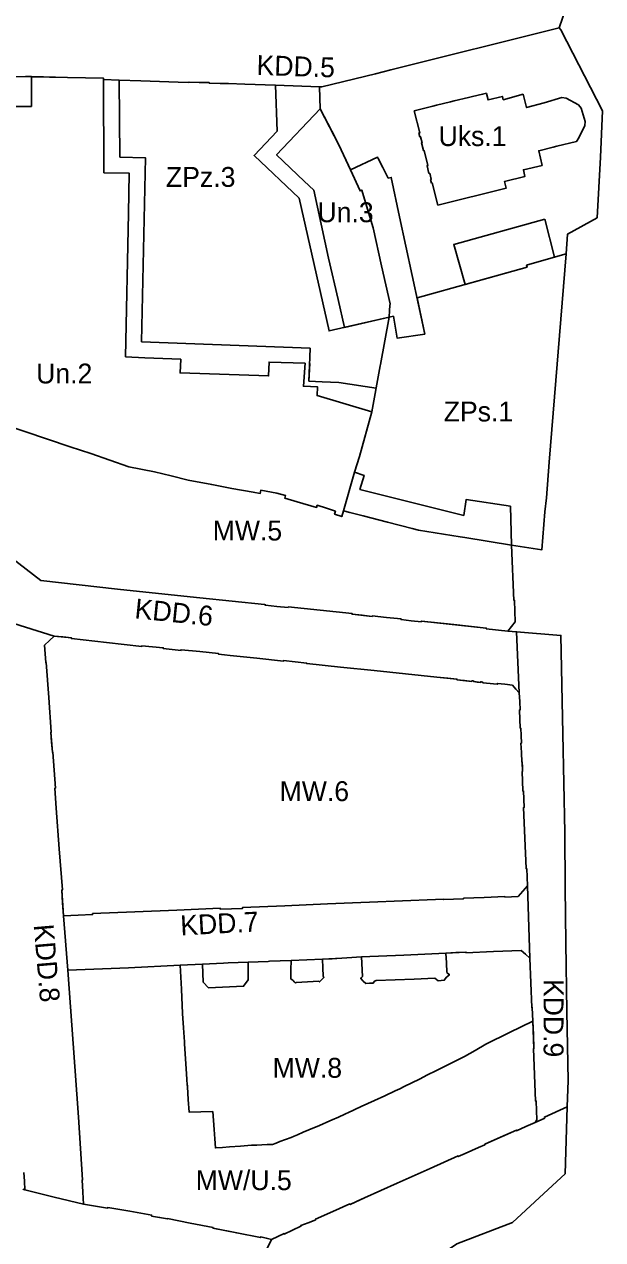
# Model space of a CAD drawing. Extents: x 7423893 to 7425332, y 5547241 to 5548246.
# Drawn here: x 7424503.9 to 7424649.3, y 5547447.3 to 5547753.2 of the extents above; entities that cross this region are included whole.
import ezdxf

# ---------------------------------------------------------------- set-up
doc = ezdxf.new("R2010")
doc.units = 0
for name, color, linetype in [('linie rozgraniczające', 7, 'Continuous'), ('nieprzekraczalne linie zabudowy', 7, 'Continuous'), ('obowiazujace linie zabudowy', 7, 'Continuous'), ('przeznaczenia terenów', 7, 'Continuous')]:
    doc.layers.add(name, color=color, linetype=linetype)

msp = doc.modelspace()

# ---------------------------------------------------------------- linework, layer by layer
at = {"layer": 'linie rozgraniczające'}
for p, q in [((7424638.32, 5547752.33), (7424647.15, 5547777.97)), ((7424527.77, 5547739.17), (7424527.86, 5547719.76)), ((7424602.61, 5547684.33), (7424604.56, 5547675.26)), ((7424575.62, 5547667.85), (7424575.42, 5547663.41)), ((7424493.58, 5547604.76), (7424511.39, 5547599.26)), ((7424612.65, 5547588.41), (7424607.57, 5547588.92)), ((7424630.36, 5547536.41), (7424630.95, 5547518.2)), ((7424514.83, 5547515.21), (7424513.72, 5547528.84)), ((7424516.17, 5547496.69), (7424514.83, 5547515.21)), ((7424566.05, 5547447.44), (7424558.82, 5547432.87))]:
    msp.add_line(p, q, dxfattribs=at)
for points in [[(7424578.1, 5547737.49), (7424578.64, 5547737.47), (7424592.15, 5547740.77), (7424596.05, 5547741.7), (7424638.32, 5547752.33)], [(7424638.32, 5547752.33), (7424638.76, 5547751.78), (7424649.27, 5547731.38), (7424648.72, 5547719.8), (7424647.91, 5547704.52), (7424640.47, 5547700.4), (7424640.07, 5547695.44), (7424635.83, 5547642.97)], [(7424490.59, 5547739.94), (7424499.64, 5547739.99), (7424504.2, 5547740.03), (7424505.66, 5547740.03), (7424514.71, 5547739.84), (7424523.77, 5547739.65), (7424523.77, 5547739.49), (7424523.77, 5547739.32), (7424527.77, 5547739.17), (7424533.17, 5547738.96), (7424542.57, 5547738.6), (7424545.24, 5547738.51), (7424545.32, 5547738.65), (7424547.84, 5547738.58), (7424550.37, 5547738.51), (7424550.36, 5547738.36), (7424553.12, 5547738.28), (7424554.49, 5547738.27), (7424555.25, 5547738.27), (7424559.28, 5547738.17), (7424567.07, 5547737.89), (7424578.1, 5547737.49)], [(7424567.45, 5547726.3), (7424567.45, 5547726.3), (7424567.07, 5547737.89)], [(7424626.37, 5547622.14), (7424614.59, 5547624.04), (7424613.49, 5547624.21), (7424602.94, 5547625.9), (7424601.4, 5547626.3), (7424595.21, 5547627.91), (7424589.03, 5547629.51), (7424585.74, 5547630.37), (7424584.11, 5547630.79), (7424586.91, 5547640.49), (7424588.13, 5547644.41), (7424591.21, 5547655.68), (7424593.34, 5547667.24), (7424593.4, 5547667.58), (7424595.59, 5547679.47), (7424595.71, 5547681.17), (7424595.81, 5547682.42), (7424595.84, 5547682.86), (7424593.71, 5547692.41), (7424591.57, 5547701.96), (7424590.15, 5547706.71), (7424588.72, 5547711.47), (7424588.28, 5547711.27), (7424585.85, 5547716.58), (7424585.34, 5547717.7), (7424582.92, 5547722.87), (7424578.28, 5547731.89), (7424578.1, 5547737.49)], [(7424572.96, 5547709.42), (7424561.63, 5547720.17), (7424567.45, 5547726.3)], [(7424533.38, 5547673.33), (7424534.34, 5547719.63), (7424527.86, 5547719.76)], [(7424595.59, 5547679.47), (7424588.6, 5547677.88), (7424580.5, 5547676.03), (7424572.96, 5547709.42)], [(7424602.61, 5547684.33), (7424630.26, 5547692.11), (7424630.15, 5547692.55), (7424635.68, 5547694.16), (7424640.07, 5547695.44)], [(7424595.59, 5547679.47), (7424596.69, 5547679.72), (7424597.59, 5547674.25), (7424604.56, 5547675.26)], [(7424533.38, 5547673.33), (7424575.76, 5547671.66)], [(7424592.31, 5547661.65), (7424582.95, 5547663.07), (7424578.76, 5547663.23), (7424575.42, 5547663.41), (7424575.69, 5547669.47), (7424575.76, 5547671.66)], [(7424492.63, 5547654.49), (7424504.02, 5547650.7), (7424515.4, 5547646.9), (7424520.64, 5547645.15), (7424525.4, 5547643.5), (7424530.16, 5547641.84), (7424536.59, 5547640.6), (7424540.84, 5547639.53), (7424545.1, 5547638.46), (7424551.01, 5547637.36), (7424556.09, 5547636.42), (7424561.4, 5547635.48), (7424563.2, 5547635.15), (7424563.32, 5547635.93), (7424567.36, 5547635.22), (7424569.52, 5547634.66), (7424569.34, 5547633.98), (7424572.51, 5547633.02), (7424577.36, 5547631.61), (7424577.53, 5547632.15), (7424579.81, 5547631.4), (7424582.09, 5547630.65), (7424581.89, 5547629.9), (7424583.69, 5547629.31), (7424584.11, 5547630.79)], [(7424635.83, 5547642.97), (7424635.11, 5547634), (7424634.77, 5547630.54), (7424633.98, 5547620.95), (7424626.37, 5547622.14)], [(7424626.37, 5547622.14), (7424626.97, 5547608.22), (7424627.13, 5547608.22), (7424627.3, 5547602.79), (7424625.45, 5547600.51), (7424619.99, 5547601.08), (7424620.01, 5547601.24), (7424603.71, 5547603.01), (7424603.69, 5547602.85), (7424601.15, 5547603.12), (7424598.61, 5547603.4), (7424598.58, 5547603.57), (7424594.97, 5547603.96), (7424591.36, 5547604.34), (7424591.33, 5547604.21), (7424586.3, 5547604.74), (7424586.3, 5547604.82), (7424586.31, 5547604.89), (7424578.27, 5547605.75), (7424570.22, 5547606.6), (7424570.19, 5547606.44), (7424567.34, 5547606.73), (7424564.5, 5547607.02), (7424564.51, 5547607.15), (7424564.29, 5547607.17), (7424556.13, 5547608), (7424547.98, 5547608.84), (7424537.66, 5547609.94), (7424527.34, 5547611.04), (7424517.69, 5547612.16), (7424508.04, 5547613.27), (7424504.38, 5547616.08), (7424500.71, 5547618.9)], [(7424625.45, 5547600.51), (7424627.63, 5547600.33), (7424628.32, 5547584.94)], [(7424632.27, 5547476.86), (7424634.73, 5547477.97), (7424634.63, 5547478.21), (7424640.36, 5547480.81), (7424640.58, 5547487.43), (7424640.29, 5547504.76), (7424640, 5547522.09), (7424639.87, 5547535.97), (7424639.73, 5547549.85), (7424639.25, 5547574.62), (7424638.78, 5547599.4), (7424627.63, 5547600.33)], [(7424607.57, 5547588.92), (7424599.69, 5547589.75), (7424591.81, 5547590.57), (7424583.34, 5547591.45), (7424574.88, 5547592.32), (7424574.88, 5547592.39), (7424574.88, 5547592.46), (7424571.95, 5547592.76), (7424569.02, 5547593.07), (7424569, 5547592.91), (7424562.31, 5547593.65), (7424555.62, 5547594.39), (7424554.17, 5547594.53), (7424552.72, 5547594.67), (7424552.73, 5547594.75), (7424552.73, 5547594.84), (7424548.02, 5547595.33), (7424543.3, 5547595.81), (7424543.29, 5547595.72), (7424543.28, 5547595.63), (7424541.04, 5547595.87), (7424538.81, 5547596.11), (7424538.8, 5547596.21), (7424538.8, 5547596.31), (7424536.13, 5547596.57), (7424533.46, 5547596.83), (7424533.44, 5547596.65), (7424524.59, 5547597.64), (7424515.74, 5547598.63), (7424515.75, 5547598.71), (7424515.76, 5547598.79), (7424511.39, 5547599.26), (7424510.19, 5547598.1), (7424508.98, 5547596.94), (7424509.12, 5547594.76), (7424509.26, 5547592.58), (7424509.4, 5547592.57), (7424510.03, 5547583.82), (7424510.65, 5547575.06), (7424510.58, 5547575.06), (7424510.52, 5547575.06), (7424510.73, 5547572.54), (7424510.94, 5547570.02), (7424511.04, 5547570.03), (7424511.38, 5547565.49), (7424511.71, 5547560.95), (7424511.62, 5547560.95), (7424511.54, 5547560.94), (7424511.71, 5547558.46), (7424511.87, 5547555.98), (7424512.67, 5547545.67), (7424513.46, 5547535.35), (7424513.38, 5547535.34), (7424513.31, 5547535.34), (7424513.52, 5547532.09), (7424513.72, 5547528.84), (7424517.4, 5547529), (7424521.07, 5547529.15), (7424521.07, 5547529.28), (7424521.07, 5547529.41), (7424531.64, 5547529.84), (7424542.21, 5547530.28), (7424547.69, 5547530.51), (7424553.16, 5547530.74), (7424553.16, 5547530.62), (7424553.16, 5547530.49), (7424555.94, 5547530.58), (7424558.71, 5547530.66), (7424558.7, 5547530.91), (7424569.38, 5547531.38), (7424580.07, 5547531.84), (7424586.42, 5547532.1), (7424592.76, 5547532.36), (7424596.9, 5547532.54), (7424601.04, 5547532.73), (7424605.17, 5547532.9), (7424609.31, 5547533.07), (7424609.32, 5547532.92), (7424611.81, 5547533.03), (7424614.3, 5547533.13), (7424614.31, 5547533.2), (7424614.32, 5547533.26), (7424619.51, 5547533.49), (7424624.7, 5547533.71), (7424624.7, 5547533.55), (7424626.35, 5547533.62), (7424628, 5547533.69), (7424629.18, 5547535.05), (7424630.36, 5547536.41), (7424630.27, 5547538.57), (7424630.18, 5547540.73), (7424630.09, 5547540.73), (7424630.01, 5547540.72), (7424629.68, 5547548.41), (7424629.35, 5547556.09), (7424629.44, 5547556.09), (7424629.52, 5547556.1), (7424629.42, 5547558.2), (7424629.33, 5547560.3), (7424629.27, 5547560.3), (7424629.2, 5547560.3), (7424629.12, 5547562.73), (7424629.03, 5547565.16), (7424629.16, 5547565.17), (7424629.12, 5547566.35), (7424629.07, 5547567.53), (7424629, 5547567.53), (7424628.94, 5547567.52), (7424628.83, 5547569.92), (7424628.73, 5547572.33), (7424628.87, 5547572.33), (7424628.78, 5547574.21), (7424628.69, 5547576.08), (7424628.62, 5547576.08), (7424628.54, 5547576.07), (7424628.44, 5547578.34), (7424628.34, 5547580.61), (7424628.43, 5547580.61), (7424628.52, 5547580.61), (7424628.42, 5547582.78), (7424628.32, 5547584.94), (7424627.46, 5547585.92), (7424626.6, 5547586.89), (7424624.7, 5547587.11), (7424622.8, 5547587.33), (7424622.78, 5547587.14), (7424619.11, 5547587.52), (7424619.12, 5547587.61), (7424619.12, 5547587.69), (7424618.81, 5547587.72), (7424618.64, 5547587.74), (7424618.62, 5547587.56), (7424617.74, 5547587.67), (7424616.85, 5547587.78), (7424616.86, 5547587.93), (7424616.38, 5547587.98), (7424616.37, 5547587.85), (7424612.63, 5547588.25), (7424612.65, 5547588.41)], [(7424514.83, 5547515.21), (7424530.04, 5547515.8), (7424543.06, 5547516.45), (7424548.64, 5547516.71), (7424553.92, 5547516.92), (7424555.11, 5547516.98), (7424560.16, 5547517.21), (7424565.18, 5547517.39), (7424565.49, 5547517.41), (7424568.21, 5547517.52), (7424570.93, 5547517.63), (7424578.82, 5547517.93), (7424583.73, 5547518.19), (7424588.67, 5547518.49), (7424599.27, 5547518.98), (7424609.87, 5547519.46), (7424614.9, 5547519.71), (7424614.9, 5547519.63), (7424614.89, 5547519.55), (7424621.84, 5547519.84), (7424628.8, 5547520.14), (7424629.88, 5547519.17), (7424630.95, 5547518.2), (7424631.19, 5547511.99), (7424631.43, 5547505.77), (7424631.59, 5547505.78), (7424631.74, 5547502.35), (7424631.86, 5547498.9), (7424631.98, 5547495.45), (7424631.92, 5547495.45), (7424631.86, 5547495.45), (7424632.12, 5547488.85), (7424632.38, 5547482.25), (7424632.56, 5547482.25), (7424632.74, 5547477.53), (7424632.5, 5547477.2), (7424632.27, 5547476.86), (7424629.96, 5547475.81), (7424627.65, 5547474.76), (7424627.62, 5547474.84), (7424627.58, 5547474.92), (7424623.61, 5547473.13), (7424619.64, 5547471.35), (7424619.69, 5547471.25), (7424618.04, 5547470.51), (7424616.4, 5547469.77), (7424614.69, 5547469.02), (7424612.98, 5547468.27), (7424612.91, 5547468.43), (7424609.41, 5547466.86), (7424605.9, 5547465.29), (7424597.64, 5547461.59), (7424589.38, 5547457.89), (7424587.59, 5547457.04), (7424585.81, 5547456.2), (7424585.74, 5547456.35), (7424581.42, 5547454.45), (7424577.1, 5547452.54), (7424577.16, 5547452.38), (7424575.27, 5547451.63), (7424573.38, 5547450.88), (7424573.44, 5547450.73), (7424571.34, 5547449.75), (7424569.25, 5547448.76), (7424569.18, 5547448.91), (7424567.62, 5547448.17), (7424566.05, 5547447.44), (7424563.34, 5547448.04), (7424563.3, 5547447.87), (7424557.3, 5547449.04), (7424551.31, 5547450.22), (7424551.35, 5547450.41), (7424545.62, 5547451.54), (7424539.89, 5547452.68), (7424539.87, 5547452.58), (7424535.88, 5547453.31), (7424535.93, 5547453.56), (7424530.4, 5547454.49), (7424524.86, 5547455.41), (7424524.81, 5547455.3), (7424518.79, 5547456.26), (7424518.59, 5547459.33), (7424518.4, 5547462.41), (7424518.52, 5547462.41), (7424518.01, 5547470.29), (7424517.5, 5547478.17), (7424516.17, 5547496.69)], [(7424551.26, 5547479.64), (7424548.29, 5547479.54), (7424545.31, 5547479.45), (7424545.1, 5547482.62), (7424544.89, 5547485.78), (7424544.88, 5547486.04), (7424544.86, 5547486.3), (7424544.77, 5547487.68), (7424544.67, 5547489.06), (7424544.42, 5547492.86), (7424544.17, 5547496.66), (7424544.14, 5547497.1), (7424543.91, 5547500.7), (7424543.67, 5547504.3), (7424543.37, 5547510.38), (7424543.06, 5547516.45)], [(7424631.74, 5547502.35), (7424625.82, 5547499.45), (7424619.9, 5547496.55), (7424617.21, 5547495), (7424614.52, 5547493.44), (7424612.99, 5547492.67), (7424607.34, 5547489.84), (7424605.28, 5547488.8), (7424603.21, 5547487.77), (7424601.31, 5547486.82), (7424599.41, 5547485.87), (7424598.28, 5547485.33), (7424597.15, 5547484.8), (7424594.55, 5547483.58), (7424591.95, 5547482.35), (7424588.6, 5547480.83), (7424585.25, 5547479.3), (7424584.83, 5547479.11), (7424584.42, 5547478.92), (7424582.83, 5547478.2), (7424581.24, 5547477.48), (7424580.66, 5547477.23), (7424578.05, 5547476.12), (7424575.45, 5547475.01), (7424573.99, 5547474.38), (7424572.52, 5547473.76), (7424571.73, 5547473.4), (7424570.93, 5547473.04), (7424569.54, 5547472.53), (7424568.16, 5547472.02)], [(7424469.69, 5547261.72), (7424483.52, 5547241.43), (7424537.6, 5547349.36), (7424562.07, 5547394.62), (7424577.11, 5547416.18), (7424595.5, 5547434.76), (7424612.59, 5547446.29), (7424626.63, 5547451.7), (7424635.53, 5547459.94), (7424639.81, 5547463.89), (7424640.36, 5547480.81)], [(7424568.16, 5547472.02), (7424567.2, 5547471.67), (7424566.24, 5547471.33), (7424564.94, 5547471.28), (7424563.63, 5547471.23), (7424562.33, 5547471.17), (7424561.02, 5547471.12), (7424558.23, 5547470.92), (7424555.44, 5547470.73), (7424553.68, 5547470.59), (7424551.92, 5547470.45), (7424551.75, 5547472.75), (7424551.59, 5547475.04), (7424551.42, 5547477.34), (7424551.26, 5547479.64)], [(7424503.74, 5547464.22), (7424503.9, 5547462.07), (7424504.05, 5547459.92), (7424503.51, 5547460.05)], [(7424504.05, 5547459.92), (7424511.42, 5547458.09), (7424518.79, 5547456.26)]]:
    msp.add_lwpolyline(points, dxfattribs=at)
at = {"layer": 'nieprzekraczalne linie zabudowy'}
for p, q in [((7424505.68, 5547732.48), (7424454.11, 5547732.54)), ((7424529.3, 5547669.51), (7424530.05, 5547705.59)), ((7424614.69, 5547687.73), (7424614.69, 5547687.73)), ((7424534.18, 5547669.3), (7424529.3, 5547669.51))]:
    msp.add_line(p, q, dxfattribs=at)
for points in [[(7424620.05, 5547735.83), (7424619.07, 5547735.59), (7424616.59, 5547735.03), (7424615.58, 5547734.79), (7424611.97, 5547733.95), (7424611.03, 5547733.72), (7424607.53, 5547732.84), (7424606.6, 5547732.61), (7424601.92, 5547731.45)], [(7424634.05, 5547717.67), (7424634.05, 5547717.67), (7424634.05, 5547717.67), (7424633.19, 5547721.38), (7424636.85, 5547722.31), (7424637.79, 5547722.53), (7424642.71, 5547723.73), (7424643.29, 5547724.61), (7424644.82, 5547727.71), (7424644.85, 5547728.73), (7424643.85, 5547732.11), (7424643.23, 5547732.93), (7424640.12, 5547734.65), (7424639.02, 5547734.81), (7424634.57, 5547733.42), (7424630.15, 5547732.22), (7424629.25, 5547735.61), (7424624.27, 5547734.19), (7424624.06, 5547735.03), (7424620.46, 5547734.16), (7424620.07, 5547735.77)], [(7424592.84, 5547719.4), (7424592.64, 5547719.78), (7424585.85, 5547716.58), (7424582.92, 5547722.87), (7424581.15, 5547726.3)], [(7424607.86, 5547707.71), (7424624.99, 5547711.92), (7424624.57, 5547713.63), (7424629.72, 5547714.92), (7424629.34, 5547716.58), (7424634.05, 5547717.67)], [(7424586.91, 5547640.49), (7424588.13, 5547644.41), (7424591.21, 5547655.68), (7424577.49, 5547659.76), (7424577.55, 5547661.98), (7424574.04, 5547662.11), (7424574.48, 5547667.89)], [(7424626.37, 5547622.14), (7424626.08, 5547631.92), (7424614.99, 5547633.64), (7424614.35, 5547629.62), (7424588.26, 5547636.15), (7424589.28, 5547639.68), (7424586.91, 5547640.49)]]:
    msp.add_lwpolyline(points, dxfattribs=at)
at = {"layer": 'obowiazujace linie zabudowy'}
msp.add_line((7424523.88, 5547715.83), (7424523.77, 5547739.23), dxfattribs=at)
for points in [[(7424505.71, 5547740), (7424505.68, 5547732.48)], [(7424523.77, 5547739.65), (7424505.71, 5547740)], [(7424523.77, 5547739.23), (7424523.77, 5547739.32), (7424523.77, 5547739.65)], [(7424581.15, 5547726.3), (7424578.28, 5547731.89), (7424567.29, 5547720.32), (7424574.23, 5547713.73), (7424576.66, 5547711.42)], [(7424601.92, 5547731.45), (7424603.28, 5547725.87), (7424603.07, 5547725.81), (7424603.32, 5547724.86), (7424603.52, 5547724.91), (7424603.89, 5547723.39), (7424603.71, 5547723.33), (7424604.21, 5547721.4), (7424604.38, 5547721.44), (7424605.31, 5547717.66), (7424605.14, 5547717.62), (7424605.61, 5547715.66), (7424605.81, 5547715.71), (7424606.19, 5547714.21), (7424606.01, 5547714.16), (7424606.25, 5547713.22), (7424606.44, 5547713.27), (7424607.87, 5547707.68)], [(7424604.56, 5547675.26), (7424598.23, 5547704.77), (7424596.11, 5547714.68), (7424595.37, 5547714.51), (7424594, 5547717.15), (7424592.84, 5547719.4)], [(7424530.05, 5547705.59), (7424530.26, 5547715.71), (7424523.88, 5547715.83)], [(7424576.66, 5547711.42), (7424580.37, 5547694.36), (7424582.78, 5547683.92), (7424584.4, 5547676.92), (7424584.4, 5547676.92)], [(7424634.73, 5547704.16), (7424611.85, 5547697.75), (7424614.69, 5547687.73)], [(7424614.69, 5547687.73), (7424630.26, 5547692.11), (7424630.15, 5547692.55), (7424635.68, 5547694.16), (7424637.19, 5547694.6), (7424634.73, 5547704.16)], [(7424584.4, 5547676.92), (7424596.69, 5547679.72), (7424597.59, 5547674.25), (7424604.56, 5547675.26)], [(7424574.48, 5547667.89), (7424565.43, 5547668.2), (7424565.31, 5547664.71), (7424543.06, 5547665.48), (7424543.22, 5547668.92), (7424534.18, 5547669.3)], [(7424625.45, 5547600.51), (7424627.3, 5547602.79), (7424627.13, 5547608.22), (7424626.97, 5547608.22), (7424626.37, 5547622.14)], [(7424500.71, 5547618.9), (7424508.04, 5547613.27), (7424517.69, 5547612.16), (7424527.34, 5547611.04), (7424537.66, 5547609.94), (7424547.98, 5547608.84), (7424556.13, 5547608), (7424564.29, 5547607.17), (7424564.51, 5547607.15), (7424564.5, 5547607.02), (7424567.34, 5547606.73), (7424570.19, 5547606.44), (7424570.22, 5547606.6), (7424578.27, 5547605.75), (7424586.31, 5547604.89), (7424586.3, 5547604.74), (7424588.82, 5547604.48), (7424591.33, 5547604.21), (7424591.36, 5547604.34), (7424594.97, 5547603.96), (7424598.58, 5547603.57), (7424598.61, 5547603.4), (7424601.15, 5547603.12), (7424603.69, 5547602.85), (7424603.71, 5547603.01), (7424611.86, 5547602.12), (7424620.01, 5547601.24), (7424619.99, 5547601.08), (7424625.45, 5547600.51)], [(7424628.32, 5547584.94), (7424627.46, 5547585.92), (7424626.6, 5547586.89), (7424624.7, 5547587.11), (7424622.8, 5547587.33), (7424622.78, 5547587.14), (7424620.95, 5547587.33), (7424619.11, 5547587.52), (7424619.12, 5547587.69), (7424618.81, 5547587.72), (7424618.64, 5547587.74), (7424618.62, 5547587.57), (7424618.62, 5547587.56), (7424616.85, 5547587.78), (7424616.86, 5547587.93), (7424616.62, 5547587.96), (7424616.38, 5547587.98), (7424616.37, 5547587.85), (7424614.5, 5547588.05), (7424612.63, 5547588.25), (7424612.65, 5547588.41), (7424612.65, 5547588.41), (7424610.39, 5547588.64), (7424607.57, 5547588.92), (7424599.69, 5547589.75), (7424591.81, 5547590.57), (7424583.34, 5547591.45), (7424574.88, 5547592.32), (7424574.88, 5547592.46), (7424571.95, 5547592.76), (7424569.02, 5547593.07), (7424569, 5547592.9), (7424562.31, 5547593.65), (7424555.62, 5547594.39), (7424554.17, 5547594.53), (7424552.72, 5547594.67), (7424552.73, 5547594.8), (7424552.73, 5547594.84), (7424548.02, 5547595.33), (7424543.3, 5547595.81), (7424543.28, 5547595.64), (7424543.28, 5547595.63), (7424541.04, 5547595.87), (7424538.81, 5547596.11), (7424538.8, 5547596.21), (7424538.8, 5547596.31), (7424536.13, 5547596.57), (7424533.46, 5547596.83), (7424533.44, 5547596.65), (7424524.59, 5547597.64), (7424515.74, 5547598.63), (7424515.76, 5547598.79), (7424513.58, 5547599.03), (7424511.39, 5547599.26), (7424510.19, 5547598.1), (7424508.98, 5547596.94), (7424509.12, 5547594.76), (7424509.26, 5547592.58), (7424509.4, 5547592.57), (7424510.03, 5547583.82), (7424510.65, 5547575.06), (7424510.52, 5547575.06), (7424510.94, 5547570.02), (7424511.04, 5547570.03), (7424511.38, 5547565.49), (7424511.71, 5547560.95), (7424511.54, 5547560.94), (7424511.71, 5547558.46), (7424511.87, 5547555.98), (7424512.67, 5547545.67), (7424513.46, 5547535.35), (7424513.29, 5547535.34), (7424513.72, 5547528.84), (7424517.4, 5547529), (7424521.07, 5547529.15), (7424521.07, 5547529.41), (7424531.64, 5547529.84), (7424542.21, 5547530.28), (7424547.69, 5547530.51), (7424553.16, 5547530.74), (7424553.16, 5547530.49), (7424555.94, 5547530.58), (7424558.71, 5547530.66), (7424558.7, 5547530.91), (7424569.38, 5547531.38), (7424580.07, 5547531.84), (7424586.42, 5547532.1), (7424592.76, 5547532.36), (7424596.9, 5547532.54), (7424601.04, 5547532.73), (7424605.17, 5547532.9), (7424609.31, 5547533.07), (7424609.32, 5547532.92), (7424611.81, 5547533.03), (7424614.3, 5547533.13), (7424614.31, 5547533.2), (7424614.32, 5547533.26), (7424619.51, 5547533.49), (7424624.7, 5547533.71), (7424624.7, 5547533.55), (7424626.35, 5547533.62), (7424628, 5547533.69), (7424629.18, 5547535.05), (7424630.36, 5547536.41), (7424630.27, 5547538.57), (7424630.18, 5547540.73), (7424630.01, 5547540.72), (7424629.68, 5547548.41), (7424629.35, 5547556.09), (7424629.52, 5547556.1), (7424629.42, 5547558.27), (7424629.33, 5547560.3), (7424629.2, 5547560.3), (7424629.11, 5547562.75), (7424629.03, 5547565.16), (7424629.16, 5547565.17), (7424629.07, 5547567.48), (7424629.07, 5547567.53), (7424628.94, 5547567.52), (7424628.83, 5547569.92), (7424628.73, 5547572.33), (7424628.87, 5547572.33), (7424628.78, 5547574.21), (7424628.69, 5547576.08), (7424628.54, 5547576.07)], [(7424628.54, 5547576.07), (7424628.34, 5547580.61), (7424628.52, 5547580.61), (7424628.42, 5547582.78), (7424628.32, 5547584.94)], [(7424514.83, 5547515.21), (7424516.17, 5547496.69), (7424517.5, 5547478.17), (7424518.01, 5547470.29), (7424518.52, 5547462.41), (7424518.4, 5547462.41), (7424518.59, 5547459.33), (7424518.79, 5547456.26), (7424521.8, 5547455.78), (7424524.81, 5547455.3), (7424524.86, 5547455.41), (7424530.4, 5547454.49), (7424535.93, 5547453.56), (7424535.88, 5547453.31), (7424537.88, 5547452.95), (7424539.87, 5547452.58), (7424539.89, 5547452.68), (7424545.62, 5547451.54), (7424551.35, 5547450.41), (7424551.32, 5547450.24), (7424557.3, 5547449.04), (7424563.3, 5547447.87), (7424563.32, 5547448.04), (7424564.7, 5547447.74), (7424566.05, 5547447.44), (7424567.62, 5547448.17), (7424569.18, 5547448.91), (7424569.25, 5547448.75), (7424571.34, 5547449.75), (7424573.44, 5547450.73), (7424573.37, 5547450.88), (7424575.27, 5547451.63), (7424577.16, 5547452.38), (7424577.1, 5547452.54), (7424581.42, 5547454.45), (7424585.74, 5547456.35), (7424585.81, 5547456.19), (7424589.38, 5547457.89), (7424597.64, 5547461.59), (7424605.9, 5547465.29), (7424609.41, 5547466.86), (7424612.91, 5547468.43), (7424612.98, 5547468.27), (7424614.69, 5547469.02), (7424616.4, 5547469.77), (7424618.04, 5547470.51), (7424619.69, 5547471.25), (7424619.64, 5547471.35), (7424627.58, 5547474.92), (7424627.65, 5547474.76), (7424629.96, 5547475.81), (7424632.27, 5547476.86), (7424632.74, 5547477.53), (7424632.56, 5547482.25), (7424632.38, 5547482.25), (7424631.86, 5547495.45), (7424631.98, 5547495.45), (7424631.74, 5547502.35), (7424631.59, 5547505.78), (7424631.43, 5547505.77), (7424631.19, 5547511.99), (7424630.95, 5547518.2), (7424629.88, 5547519.17), (7424628.8, 5547520.14), (7424621.84, 5547519.84), (7424614.89, 5547519.55), (7424614.9, 5547519.71), (7424612.38, 5547519.58), (7424609.87, 5547519.46)], [(7424609.87, 5547519.46), (7424610, 5547517.04), (7424610.13, 5547514.61), (7424610.75, 5547514.03), (7424609.99, 5547513.4), (7424609.43, 5547512.62), (7424607.89, 5547512.53), (7424607.07, 5547513.16), (7424601.89, 5547512.93), (7424597.12, 5547512.75), (7424592.35, 5547512.57), (7424592.13, 5547512.5), (7424591.91, 5547512.42), (7424591.76, 5547512.17), (7424591.61, 5547511.93), (7424590.66, 5547511.88), (7424589.71, 5547511.82), (7424589.08, 5547512.43), (7424588.44, 5547513.04), (7424588.69, 5547513.33), (7424588.93, 5547513.61), (7424588.67, 5547518.49), (7424586.2, 5547518.34), (7424583.73, 5547518.19), (7424581.28, 5547518.06), (7424578.82, 5547517.93), (7424578.91, 5547515.8), (7424579, 5547513.67), (7424579.18, 5547513.35), (7424578.11, 5547512.23), (7424577.91, 5547512.37), (7424575.06, 5547512.24), (7424572.21, 5547512.11), (7424571.99, 5547511.95), (7424571.74, 5547512.26), (7424571.49, 5547512.57), (7424571.21, 5547512.77), (7424570.92, 5547512.97), (7424570.92, 5547515.3), (7424570.93, 5547517.63), (7424565.49, 5547517.41), (7424565.18, 5547517.39), (7424560.16, 5547517.21), (7424560.18, 5547512.78), (7424559.02, 5547511.14), (7424550.16, 5547510.75), (7424548.87, 5547512.14), (7424548.64, 5547516.71), (7424543.06, 5547516.45), (7424530.04, 5547515.8), (7424514.83, 5547515.21)]]:
    msp.add_lwpolyline(points, dxfattribs=at)

# ---------------------------------------------------------------- texts
at = {"layer": 'przeznaczenia terenów'}
for s, rotation, p in [('KDD.5', 358.1485, (7424562.21, 5547740.46)), ('KDD.6', 354.1792, (7424531.47, 5547603.74)), ('KDD.7', 2.9844, (7424543.23, 5547523.91)), ('KDD.8', 274.8861, (7424506.23, 5547526.55)), ('KDD.9', 270, (7424634.43, 5547512.95))]:
    msp.add_text(s, height=5, rotation=rotation, dxfattribs=at).set_placement(p)
for s, p in [('Uks.1', (7424608.02, 5547722.56)), ('ZPz.3', (7424539.5, 5547712.29)), ('Un.3', (7424577.58, 5547703.39)), ('Un.2', (7424506.86, 5547662.82)), ('ZPs.1', (7424609.31, 5547653.26)), ('MW.5', (7424551.25, 5547623.3)), ('MW.6', (7424568.07, 5547557.72)), ('MW.8', (7424566.31, 5547488.1)), ('MW/U.5', (7424546.97, 5547459.82))]:
    msp.add_text(s, height=5, dxfattribs=at).set_placement(p)

doc.saveas('drawing.dxf')
